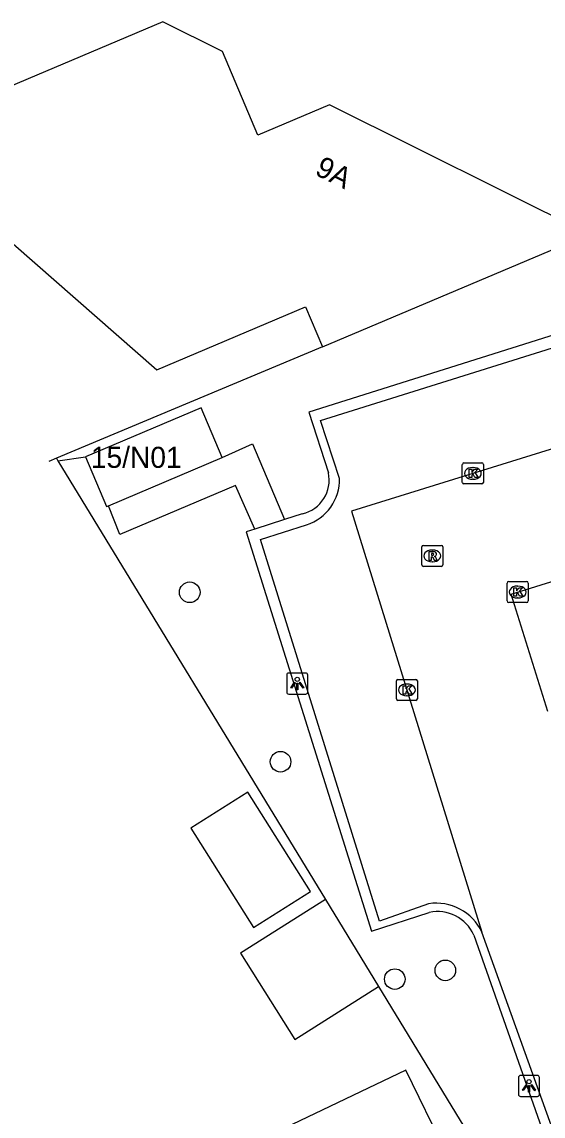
# Model space of a CAD drawing. Extents: x 161354 to 161876, y 382161 to 382804.
# Drawn here: x 161654.8 to 161679.5, y 382419.2 to 382471.2 of the extents above; entities that cross this region are included whole.
import ezdxf

# ---------------------------------------------------------------- set-up
doc = ezdxf.new("R2010")
doc.units = 0
for name, color, linetype in [('IMGEO_Boom', 7, 'Continuous'), ('IMGEO_Groenvoorziening', 7, 'Continuous'), ('IMGEO_Kolk', 7, 'Continuous'), ('IMGEO_Lichtpunt', 7, 'Continuous'), ('IMGEO_Muur', 7, 'Continuous'), ('IMGEO_Pand', 7, 'Continuous'), ('IMGEO_Pand_nummerreeks', 7, 'Continuous'), ('IMGEO_Rijbaan_lokaal_open', 7, 'Continuous'), ('IMGEO_Rioolput', 7, 'Continuous'), ('IMGEO_Voetpad_open', 7, 'Continuous')]:
    doc.layers.add(name, color=color, linetype=linetype)

msp = doc.modelspace()

# ---------------------------------------------------------------- linework, layer by layer
at = {"layer": 'IMGEO_Boom'}
for centre in [(161662.746, 382444.097), (161667.06, 382436.052), (161674.886, 382426.146), (161672.486, 382425.731)]:
    msp.add_circle(centre, 0.489, dxfattribs=at)
at = {"layer": 'IMGEO_Groenvoorziening'}
for points in [[(161669.049, 382455.744), (161656.418, 382450.464), (161656.486, 382450.341)], [(161656.486, 382450.341), (161657.793, 382450.53)], [(161656.486, 382450.341), (161669.192, 382429.513)], [(161671.714, 382425.377), (161684.318, 382404.716), (161686.096, 382401.801), (161715.999, 382413.294)]]:
    msp.add_lwpolyline(points, dxfattribs=at)
at = {"layer": 'IMGEO_Kolk'}
for p, q in [((161675.695, 382449.317), (161675.695, 382450.169)), ((161675.77, 382450.243), (161676.622, 382450.243)), ((161676.183, 382450.023), (161676.208, 382450.023)), ((161676.696, 382450.169), (161676.696, 382449.317)), ((161676.206, 382449.463), (161676.181, 382449.463)), ((161676.622, 382449.243), (161675.77, 382449.243)), ((161677.823, 382443.684), (161677.823, 382444.536)), ((161677.898, 382444.61), (161678.75, 382444.61)), ((161678.311, 382444.39), (161678.336, 382444.39)), ((161678.824, 382444.536), (161678.824, 382443.684)), ((161678.334, 382443.83), (161678.309, 382443.83)), ((161678.75, 382443.61), (161677.898, 382443.61)), ((161672.561, 382439.037), (161672.561, 382439.889)), ((161672.636, 382439.963), (161673.488, 382439.963)), ((161673.049, 382439.743), (161673.074, 382439.743)), ((161673.562, 382439.889), (161673.562, 382439.037)), ((161673.072, 382439.183), (161673.047, 382439.183)), ((161673.488, 382438.963), (161672.636, 382438.963))]:
    msp.add_line(p, q, dxfattribs=at)
for points in [[(161675.695, 382449.317), (161675.695, 382450.169)], [(161675.77, 382450.243), (161676.622, 382450.243)], [(161676.016, 382449.943), (161676.139, 382449.943), (161676.139, 382449.792), (161676.269, 382449.943), (161676.433, 382449.943), (161676.287, 382449.792), (161676.44, 382449.543), (161676.288, 382449.543), (161676.203, 382449.707), (161676.139, 382449.64), (161676.139, 382449.543), (161676.016, 382449.543), (161676.016, 382449.943)], [(161676.696, 382450.169), (161676.696, 382449.317)], [(161676.622, 382449.243), (161675.77, 382449.243)], [(161677.823, 382443.684), (161677.823, 382444.536)], [(161677.898, 382444.61), (161678.75, 382444.61)], [(161678.144, 382444.31), (161678.267, 382444.31), (161678.267, 382444.159), (161678.397, 382444.31), (161678.561, 382444.31), (161678.415, 382444.159), (161678.568, 382443.91), (161678.416, 382443.91), (161678.331, 382444.074), (161678.267, 382444.007), (161678.267, 382443.91), (161678.144, 382443.91), (161678.144, 382444.31)], [(161678.824, 382444.536), (161678.824, 382443.684)], [(161678.75, 382443.61), (161677.898, 382443.61)], [(161672.561, 382439.037), (161672.561, 382439.889)], [(161672.636, 382439.963), (161673.488, 382439.963)], [(161672.882, 382439.663), (161673.005, 382439.663), (161673.005, 382439.512), (161673.135, 382439.663), (161673.299, 382439.663), (161673.153, 382439.512), (161673.306, 382439.263), (161673.154, 382439.263), (161673.069, 382439.427), (161673.005, 382439.36), (161673.005, 382439.263), (161672.882, 382439.263), (161672.882, 382439.663)], [(161673.562, 382439.889), (161673.562, 382439.037)], [(161673.488, 382438.963), (161672.636, 382438.963)]]:
    msp.add_lwpolyline(points, dxfattribs=at)
for centre, start, end in [((161675.772, 382450.167), 91.552, 178.448), ((161675.772, 382450.167), 91.552, 178.448), ((161676.62, 382450.167), 1.552, 88.448), ((161676.62, 382450.167), 1.552, 88.448), ((161675.772, 382449.319), 181.552, 268.448), ((161675.772, 382449.319), 181.552, 268.448), ((161676.62, 382449.319), 271.552, 358.448), ((161676.62, 382449.319), 271.552, 358.448), ((161677.9, 382444.534), 91.552, 178.448), ((161677.9, 382444.534), 91.552, 178.448), ((161678.748, 382444.534), 1.552, 88.448), ((161678.748, 382444.534), 1.552, 88.448), ((161677.9, 382443.686), 181.552, 268.448), ((161677.9, 382443.686), 181.552, 268.448), ((161678.748, 382443.686), 271.552, 358.448), ((161678.748, 382443.686), 271.552, 358.448), ((161672.638, 382439.887), 91.552, 178.448), ((161672.638, 382439.887), 91.552, 178.448), ((161673.486, 382439.887), 1.552, 88.448), ((161673.486, 382439.887), 1.552, 88.448), ((161672.638, 382439.039), 181.552, 268.448), ((161672.638, 382439.039), 181.552, 268.448), ((161673.486, 382439.039), 271.552, 358.448), ((161673.486, 382439.039), 271.552, 358.448)]:
    msp.add_arc(centre, 0.0765, start, end, dxfattribs=at)
for centre, major_axis, ratio, start_param, end_param in [((161676.182, 382449.743), (-0.387, 0.002), 0.722429, 4.712389, 7.853982), ((161676.207, 382449.743), (-0.39, 0.002), 0.717154, 1.570796, 4.712389), ((161678.31, 382444.11), (-0.387, 0.002), 0.722429, 4.712389, 7.853982), ((161678.335, 382444.11), (-0.39, 0.002), 0.717154, 1.570796, 4.712389), ((161673.048, 382439.463), (-0.387, 0.002), 0.722429, 4.712389, 7.853982), ((161673.073, 382439.463), (-0.39, 0.002), 0.717154, 1.570796, 4.712389)]:
    msp.add_ellipse(centre, major_axis=major_axis, ratio=ratio, start_param=start_param, end_param=end_param, dxfattribs=at)
at = {"layer": 'IMGEO_Lichtpunt'}
for p, q in [((161667.355, 382440.167), (161667.355, 382439.36)), ((161667.355, 382440.167), (161667.355, 382439.36)), ((161668.257, 382440.262), (161667.449, 382440.262)), ((161668.257, 382440.262), (161667.449, 382440.262)), ((161668.351, 382439.36), (161668.351, 382440.167)), ((161668.351, 382439.36), (161668.351, 382440.167)), ((161667.449, 382439.266), (161668.257, 382439.266)), ((161667.449, 382439.266), (161668.257, 382439.266)), ((161678.363, 382421.062), (161678.363, 382420.255)), ((161678.363, 382421.062), (161678.363, 382420.255)), ((161679.265, 382421.157), (161678.457, 382421.157)), ((161679.265, 382421.157), (161678.457, 382421.157)), ((161679.359, 382420.255), (161679.359, 382421.062)), ((161679.359, 382420.255), (161679.359, 382421.062)), ((161678.457, 382420.161), (161679.265, 382420.161)), ((161678.457, 382420.161), (161679.265, 382420.161))]:
    msp.add_line(p, q, dxfattribs=at)
for points in [[(161667.729, 382439.831), (161667.768, 382439.803), (161667.58, 382439.541), (161667.542, 382439.568), (161667.729, 382439.831)], [(161667.831, 382439.783), (161667.878, 382439.783), (161667.878, 382439.461), (161667.831, 382439.461), (161667.831, 382439.783)], [(161667.941, 382439.803), (161667.979, 382439.83), (161668.166, 382439.568), (161668.127, 382439.54), (161667.941, 382439.803)], [(161678.737, 382420.726), (161678.776, 382420.698), (161678.588, 382420.436), (161678.55, 382420.463), (161678.737, 382420.726)], [(161678.839, 382420.678), (161678.886, 382420.678), (161678.886, 382420.356), (161678.839, 382420.356), (161678.839, 382420.678)], [(161678.949, 382420.698), (161678.987, 382420.725), (161679.174, 382420.463), (161679.135, 382420.435), (161678.949, 382420.698)]]:
    msp.add_lwpolyline(points, dxfattribs=at)
for centre in [(161667.854, 382439.965), (161678.862, 382420.86)]:
    msp.add_circle(centre, 0.0994, dxfattribs=at)
for centre, start, end in [((161667.449, 382440.167), 90, 180), ((161667.449, 382440.167), 90, 180), ((161668.257, 382440.167), 0, 90), ((161668.257, 382440.167), 0, 90), ((161667.449, 382439.36), 180, 270), ((161667.449, 382439.36), 180, 270), ((161668.257, 382439.36), 270, 0), ((161668.257, 382439.36), 270, 360), ((161678.457, 382421.062), 90, 180), ((161678.457, 382421.062), 90, 180), ((161679.265, 382421.062), 0, 90), ((161679.265, 382421.062), 0, 90), ((161678.457, 382420.255), 180, 270), ((161678.457, 382420.255), 180, 270), ((161679.265, 382420.255), 270, 0), ((161679.265, 382420.255), 270, 360)]:
    msp.add_arc(centre, 0.0946, start, end, dxfattribs=at)
at = {"layer": 'IMGEO_Muur'}
for points in [[(161669.049, 382455.744), (161656.418, 382450.464)], [(161656.418, 382450.464), (161656.053, 382450.312)]]:
    msp.add_lwpolyline(points, dxfattribs=at)
at = {"layer": 'IMGEO_Pand'}
for points in [[(161681.721, 382461.108), (161669.386, 382467.241), (161665.986, 382465.802), (161664.308, 382469.766), (161661.465, 382471.179), (161648.556, 382465.714), (161661.181, 382454.657), (161668.243, 382457.647), (161669.049, 382455.744)], [(161669.049, 382455.744), (161681.721, 382461.108)], [(161664.293, 382450.5), (161663.297, 382452.856), (161657.793, 382450.53)], [(161657.793, 382450.53), (161658.79, 382448.171), (161658.88, 382448.209)], [(161658.88, 382448.209), (161664.293, 382450.5)], [(161662.797, 382432.898), (161665.771, 382428.186), (161668.484, 382429.899), (161665.51, 382434.611), (161662.797, 382432.898)], [(161669.192, 382429.513), (161665.156, 382426.965), (161667.742, 382422.869), (161671.714, 382425.377)], [(161669.192, 382429.513), (161671.714, 382425.377)], [(161636.252, 382409.22), (161636.452, 382408.896), (161636.199, 382407.826), (161637.308, 382406.031), (161638.327, 382405.79), (161639.922, 382403.207), (161648.641, 382408.593), (161649.272, 382407.573), (161652.769, 382409.734), (161654.294, 382407.267), (161674.898, 382417.547), (161673.007, 382421.401), (161655.721, 382413.148), (161655.721, 382412.125), (161654.719, 382411.506), (161652.814, 382414.592), (161649.284, 382412.411), (161647.113, 382415.927)]]:
    msp.add_lwpolyline(points, dxfattribs=at)
at = {"layer": 'IMGEO_Rijbaan_lokaal_open'}
for points in [[(161712.68, 382423.888), (161705.505, 382446.629), (161703.303, 382453.61), (161701.999, 382457.743), (161670.433, 382447.954), (161676.627, 382427.958)], [(161679.752, 382438.431), (161678.017, 382444.015), (161698.227, 382450.298), (161700.04, 382444.393)], [(161685.748, 382408.739), (161683.749, 382408.125), (161676.627, 382427.958)]]:
    msp.add_lwpolyline(points, dxfattribs=at)
at = {"layer": 'IMGEO_Rioolput'}
for p, q in [((161673.844, 382446.324), (161674.696, 382446.324)), ((161673.769, 382445.398), (161673.769, 382446.25)), ((161674.257, 382446.104), (161674.282, 382446.104)), ((161674.77, 382446.25), (161674.77, 382445.398)), ((161674.696, 382445.324), (161673.844, 382445.324)), ((161674.28, 382445.544), (161674.255, 382445.544))]:
    msp.add_line(p, q, dxfattribs=at)
for points in [[(161673.844, 382446.324), (161674.696, 382446.324)], [(161673.769, 382445.398), (161673.769, 382446.25)], [(161674.358, 382446.022), (161674.106, 382446.024), (161674.106, 382445.624)], [(161674.106, 382445.624), (161674.23, 382445.624), (161674.23, 382445.786), (161674.241, 382445.786)], [(161674.284, 382445.943), (161674.23, 382445.943), (161674.23, 382445.862)], [(161674.23, 382445.862), (161674.282, 382445.862)], [(161674.77, 382446.25), (161674.77, 382445.398)], [(161674.696, 382445.324), (161673.844, 382445.324)], [(161674.288, 382445.757), (161674.359, 382445.624), (161674.499, 382445.624), (161674.434, 382445.75)]]:
    msp.add_lwpolyline(points, dxfattribs=at)
for centre, radius, start, end in [((161673.846, 382446.248), 0.0765, 91.552, 178.448), ((161673.846, 382446.248), 0.0765, 91.552, 178.448), ((161674.694, 382446.248), 0.0765, 1.552, 88.448), ((161674.694, 382446.248), 0.0765, 1.552, 88.448), ((161674.24, 382445.733), 0.0533, 26.0293, 88.6989), ((161674.266, 382446.051), 0.19, 274.7715, 282.9687), ((161674.29, 382445.847), 0.0964, 77.0061, 93.1865), ((161674.304, 382445.904), 0.0378, 276.6634, 79.6772), ((161674.357, 382445.912), 0.109, 350.3612, 89.416), ((161674.355, 382445.912), 0.112, 277.5842, 350.9817), ((161674.339, 382445.697), 0.108, 29.5134, 73.7905), ((161673.846, 382445.4), 0.0765, 181.552, 268.448), ((161673.846, 382445.4), 0.0765, 181.552, 268.448), ((161674.694, 382445.4), 0.0765, 271.552, 358.448), ((161674.694, 382445.4), 0.0765, 271.552, 358.448)]:
    msp.add_arc(centre, radius, start, end, dxfattribs=at)
for centre, major_axis, ratio, start_param, end_param in [((161674.256, 382445.824), (-0.387, 0.002), 0.722429, 4.712389, 7.853982), ((161674.281, 382445.824), (-0.39, 0.002), 0.717154, 1.570796, 4.712389)]:
    msp.add_ellipse(centre, major_axis=major_axis, ratio=ratio, start_param=start_param, end_param=end_param, dxfattribs=at)
at = {"layer": 'IMGEO_Voetpad_open'}
for points in [[(161669.864, 382449.504), (161668.956, 382452.261), (161700.65, 382462.177), (161701.369, 382459.788)], [(161689.44, 382459.283), (161668.411, 382452.654), (161669.333, 382449.775)], [(161664.293, 382450.5), (161665.734, 382451.143), (161667.244, 382447.55)], [(161665.834, 382447.094), (161664.926, 382449.163), (161659.419, 382446.843), (161658.88, 382448.209)], [(161667.244, 382447.55), (161665.834, 382447.094)], [(161668.095, 382447.826), (161667.244, 382447.55)], [(161665.834, 382447.094), (161665.429, 382446.963), (161671.388, 382428.011), (161674.125, 382428.894)], [(161674.091, 382429.308), (161671.753, 382428.488), (161666.101, 382446.604), (161668.298, 382447.298)], [(161676.244, 382427.823), (161681.175, 382413.785), (161683.56, 382407.517), (161685.375, 382408.079), (161686.724, 382403.784), (161704.774, 382409.388), (161704.689, 382409.909)]]:
    msp.add_lwpolyline(points, dxfattribs=at)
for centre, radius, start, end in [((161667.73, 382449.425), 1.641, 282.8525, 12.3003), ((161667.597, 382449.455), 2.268, 288.0141, 1.2454), ((161674.449, 382426.924), 2.411, 25.4023, 98.5419), ((161674.526, 382427.056), 1.881, 24.0528, 102.3207)]:
    msp.add_arc(centre, radius, start, end, dxfattribs=at)

# ---------------------------------------------------------------- texts
at = {"layer": 'IMGEO_Pand_nummerreeks'}
msp.add_text('9A', height=1, rotation=333.5639, dxfattribs=at).set_placement((161668.64, 382463.949))
msp.add_text('15/N01', height=1, dxfattribs=at).set_placement((161658.05, 382450.005))

doc.saveas('drawing.dxf')
